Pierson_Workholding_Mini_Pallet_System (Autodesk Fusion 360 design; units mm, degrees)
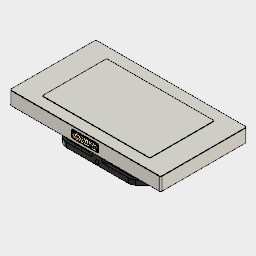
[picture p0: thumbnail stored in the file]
base_feature "Base Feature1"
base_feature "Base Feature1"
ground "Ground1"
base_feature "Base Feature1"
base_feature "Base Feature1"
joint_origin "JointOrigin1" OffsetX 0 OffsetY 0 OffsetZ 0 AngleZ 0
joint "Assemble1" alignAngle 0 alignOffsetX 0 alignOffsetY 0 alignOffsetZ 0
base_feature "Base Feature1"
base_feature "Base Feature1"
joint "Assemble1" alignAngle 0 alignOffsetX 0 alignOffsetY 0 alignOffsetZ 0
joint "Assemble1" alignAngle 0 alignOffsetX 0 alignOffsetY 0 alignOffsetZ 1.27
joint "Assemble2" alignAngle 0 alignOffsetX 0 alignOffsetY 0 alignOffsetZ 1.27
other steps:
create_component "CreateComponent1"
create_component "CreateComponent1"
create_component "CreateComponent2"
create_component "CreateComponent2"
create_component "CreateComponent1"
create_component "CreateComponent2"
joint_origin "JointOrigin1" OffsetX 0 OffsetY 0 OffsetZ 0 AngleZ 0
joint_origin "JointOrigin2" OffsetX 0 OffsetY 0 OffsetZ 0 AngleZ 0
create_component "CreateComponent3"
create_component "CreateComponent1"
create_component "CreateComponent2"
joint_origin "JointOrigin1" OffsetX 0 OffsetY 0 OffsetZ 0 AngleZ 0
joint_origin "JointOrigin1" OffsetX 0 OffsetY 0 OffsetZ 0 AngleZ 0
joint_origin "JointOrigin3" OffsetX 0 OffsetY 0 OffsetZ 0 AngleZ 0
joint_origin "JointOrigin1" OffsetX 0 OffsetY 0 OffsetZ 0 AngleZ 0
joint_origin "JointOrigin2" OffsetX 0 OffsetY 0 OffsetZ 0 AngleZ 0
joint_origin "JointOrigin2" OffsetX 0 OffsetY 0 OffsetZ 0 AngleZ 0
